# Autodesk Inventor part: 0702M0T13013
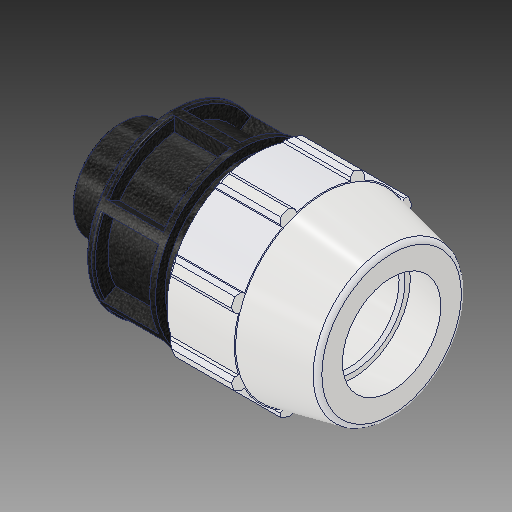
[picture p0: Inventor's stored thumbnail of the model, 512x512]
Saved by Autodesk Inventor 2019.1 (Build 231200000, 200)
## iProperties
Created: 2017-02
Part Number: 0702M0T13013
Material: PVC-Piping
Description: PLASSON MALE ADAPTOR 1 1/4'' - 1 1/4''M
Document SubType Name: Modeling
Designer: KIM
Mass: 92.6774 g
Surface Area: 199.44 cm^2
Volume: 66.1981 cm^3
Density: 1.4 g/cm^3
Appearance: PTFE
Author: KIM
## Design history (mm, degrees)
derived "0702M0T.ipt"
feature "Solid1::0702M0T.ipt"
tag "TaggingFeature1"
body "Solid1"
other parameters: "d2" = 42.1, "d4" = 16.58257, "d5" = 29.0195, "d7" = 82.042, "d8" = 61.5315, "d9" = 16.58257, "d11" = 3.31651, "d12" = 65.6336, "d13" = 120 deg, "d14" = 63.15, "d15" = 12 deg, "d16" = 73.8378, "d18" = 2.105, "d19" = 35 deg, "d20" = 17.5 deg, "d21" = 76.29906, "d23" = 0, "d25" = 360 deg, "d27" = 1.64084, "d34" = 4.1021, "d36" = 0, "d42" = 29.0195, "d43" = 2.46126, "d46" = 1.263, "d51" = 116.078, "d52" = 22.098, "d53" = 0.842, "d55" = 360 deg, "d57" = 41.91, "d58" = 29.337, "d59" = 23.2156, "d61" = 27.178, "d_" = 42.1, "E_" = 82.042, "H_" = 116.078, "l_" = 87.884, "l_2" = 22.098, "G_" = 41.91
